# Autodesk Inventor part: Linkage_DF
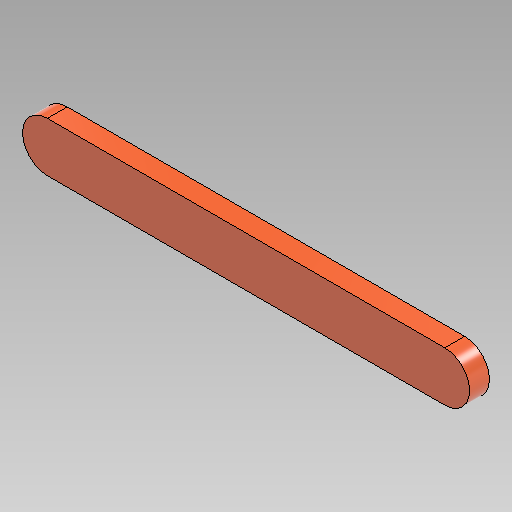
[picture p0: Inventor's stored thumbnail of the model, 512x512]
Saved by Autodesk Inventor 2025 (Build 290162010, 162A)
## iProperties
Created: 2024-10
Part Number: Linkage_DF
Material: Generic
Document SubType Name: Modeling
Designer: Dennis
Density: 1 g/cm^3
Appearance: Smooth - Light Orange
Mass: 0.43927 g
Surface Area: 6.30686 cm^2
Volume: 0.43927 cm^3
Author: Dennis
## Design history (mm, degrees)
sketch "Sketch1"
  geometry: L1 (0, 0)-(40, 0); L2 (0, -2.5)-(40, -2.5); L3 (40, 2.5)-(0, 2.5); A1 r 2.5 centre (0, 0) between (0, 2.5) and (0, -2.5); A2 r 2.5 centre (40, 0) between (40, -2.5) and (40, 2.5); 1 further point
  constraints: 8 end point, 4 point on circle, 4 tangent, 2 centre point, 1 horizontal, 1 midpoint, 1 parallel
  dimensions: "d0" = 5 distance between parallel lines of L2 L3 (= w_); "d1" = 40 distance of L1.start L1.end (= DF_)
extrude "Extrusion1" new body sketch "Sketch1" stored distance "d2" = 2 (= t_); taper "d3" = 0 deg
body "Solid1"
other parameters: "DF_" = 40 [user parameter; used in 1 equation term], "w_" = 5 [user parameter; used in 1 equation term], "t_" = 2 [user parameter; used in 1 equation term]
